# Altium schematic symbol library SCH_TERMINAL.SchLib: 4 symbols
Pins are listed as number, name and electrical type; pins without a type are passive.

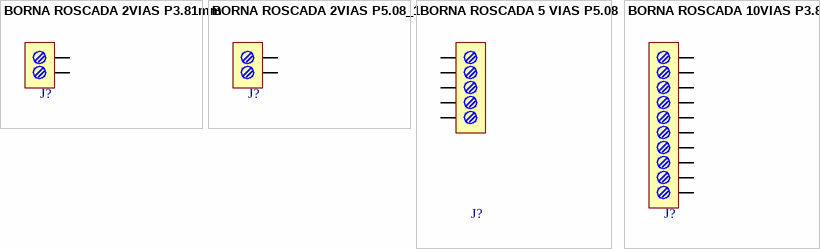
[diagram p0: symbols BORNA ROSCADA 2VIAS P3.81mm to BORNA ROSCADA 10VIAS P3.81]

## BORNA ROSCADA 2VIAS P3.81mm
designator J?
Terminal atornillable para PCB negro 2 vías,3.81mm; PCB DECAL: BORNA ROSCADA 2V P5.08; Ref. Mafero: 1457
footprint BORNA ROSCADA 2V P5.08 (Terminal roscado vertical 2 vías,5.08mm)
footprint BORNA ROSCADA 2V P3.81 (Terminal roscado vertical 2 vías,3.81mm)
footprint BORNA ROSCADA 2V P3.81 (Terminal roscado vertical 2 vías,3.81mm)
footprint BORNA ROSCADA 2V P3.81 (Terminal roscado vertical 2 vías,3.81mm)
pins: 1 (power), 2 (power)

## BORNA ROSCADA 2VIAS P5.08_1
designator J?
Terminal atornillable para PCB negro 2 vías,5.08mm; PCB DECAL: BORNA ROSCADA 2V P5.08; Ref. Mafero: 1457
footprint BORNA ROSCADA 2V P5.08 (Terminal roscado vertical 2 vías,5.08mm)
pins: 1 (power), 2 (power)

## BORNA ROSCADA 5 VIAS P5.08
designator J?
Terminal roscado vertical 5 vías, 5.08mm; Manufacturer #1: Phoenix Contact; Part Number: 1727094; Ref. Mafero: 860
footprint BORNA ROSCADA 5V P5.08 (Terminal roscado vertical 5 vías,5.08mm)
pins: 1 (power), 2 (power), 3, 4, 5

## BORNA ROSCADA 10VIAS P3.81
designator J?
Terminal roscado vertical 10 vías,3.81mm; Manufacturer #1: Phoenix Contact; Part Number: 1727094; Ref. Mafero: 860
footprint BORNA ROSCADA 10V P3.81 (Terminal roscado vertical 2 vías,3.81mm)
pins: 1 (power), 2 (power), 3, 4, 5, 6, 7, 8, 9, 10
